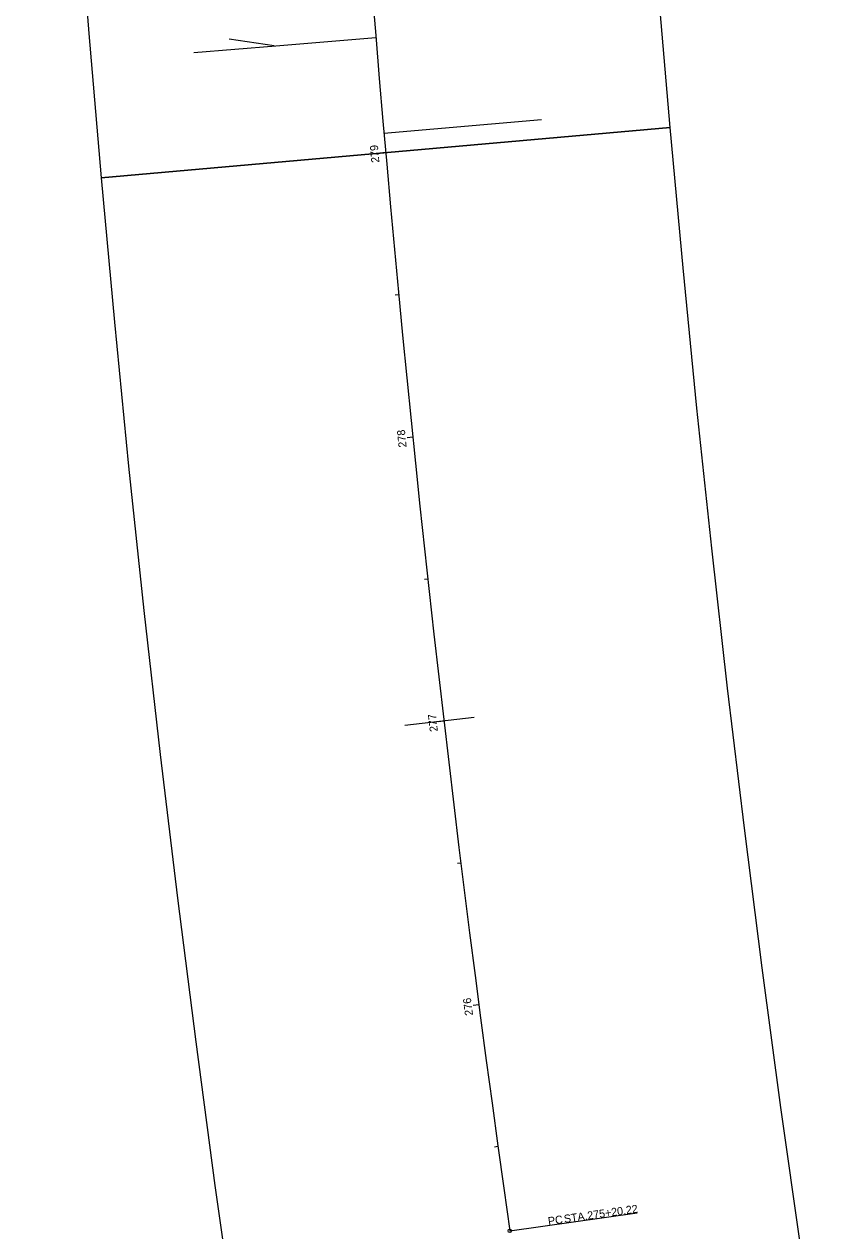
# Model space of a CAD drawing. Extents: x 1722814 to 1723176, y 329127 to 332105.
# Drawn here: x 1722817.9 to 1723103.9, y 330450.2 to 330872.4 of the extents above; entities that cross this region are included whole.
import ezdxf

# ---------------------------------------------------------------- set-up
doc = ezdxf.new("R2010")
doc.units = 0
for name, color, linetype in [('DR_P_Cells', 7, 'Continuous'), ('DR_P_Storm_Sewer', 7, 'Continuous'), ('DR_X_Cells', 7, 'Continuous'), ('DT_X_Triangles', 7, 'Continuous'), ('GE_P_Alignment', 7, 'Continuous'), ('HY_X_Wetland_Cells', 7, 'Continuous'), ('Wetland', 7, 'Continuous')]:
    doc.layers.add(name, color=color, linetype=linetype)

msp = doc.modelspace()

# ---------------------------------------------------------------- linework, layer by layer
at = {"layer": 'DR_P_Cells'}
for p, q in [((1722944.5, 330827.47), (1722942.51, 330827.29)), ((1722949.08, 330777.68), (1722947.88, 330777.57)), ((1722954, 330727.92), (1722952.01, 330727.72)), ((1722959.27, 330678.2), (1722958.07, 330678.07)), ((1722964.88, 330628.52), (1722962.9, 330628.29)), ((1722970.85, 330578.88), (1722969.66, 330578.73)), ((1722977.16, 330529.27), (1722975.17, 330529.02)), ((1722983.81, 330479.72), (1722982.62, 330479.56))]:
    msp.add_line(p, q, dxfattribs=at)
at = {"layer": 'DR_P_Storm_Sewer'}
msp.add_line((1722975.5, 330629.83), (1722951.16, 330626.99), dxfattribs=at)
at = {"layer": 'DR_X_Cells'}
for points in [[(1722844.89, 330818.67), (1723044.12, 330836.27), (1723039.95, 330885.4), (1723036.12, 330934.55), (1723032.64, 330983.73), (1723029.5, 331032.93), (1723026.71, 331082.15), (1723024.26, 331131.39), (1723022.15, 331180.65), (1723020.39, 331229.92), (1723018.97, 331279.2), (1723017.9, 331328.49), (1722817.93, 331324.83), (1722819.04, 331274.14), (1722820.49, 331223.47), (1722822.31, 331172.8), (1722824.47, 331122.15), (1722826.99, 331071.52), (1722829.87, 331020.9), (1722833.09, 330970.3), (1722836.67, 330919.73), (1722840.61, 330869.19)], [(1722905.85, 330317.14), (1723103.86, 330345.27), (1723096.82, 330394.77), (1723089.79, 330444.28), (1723082.87, 330493.38), (1723076.31, 330542.24), (1723070.09, 330591.15), (1723064.21, 330640.1), (1723058.67, 330689.09), (1723053.48, 330738.11), (1723048.63, 330787.18), (1723044.12, 330836.27), (1722844.89, 330818.67), (1722849.53, 330768.18), (1722854.52, 330717.73), (1722859.86, 330667.32), (1722865.56, 330616.94), (1722871.6, 330566.6), (1722878, 330516.31), (1722884.75, 330466.06), (1722891.78, 330416.14), (1722898.81, 330366.64)]]:
    msp.add_lwpolyline(points, close=True, dxfattribs=at)
at = {"layer": 'DT_X_Triangles'}
msp.add_line((1722905.43, 330864.84), (1722889.74, 330867.17), dxfattribs=at)
at = {"layer": 'GE_P_Alignment'}
for p, q in [((1722906.07, 330864.75), (1722877.37, 330862.38)), ((1722941.07, 330867.64), (1722906.07, 330864.75)), ((1722941.07, 330867.64), (1722906.07, 330864.75)), ((1722943.91, 330834.26), (1722999.05, 330839.08))]:
    msp.add_line(p, q, dxfattribs=at)
at = {"layer": 'HY_X_Wetland_Cells'}
msp.add_line((1722987.94, 330450.23), (1723032.49, 330456.56), dxfattribs=at)
msp.add_circle((1722987.94, 330450.23), 0.6, dxfattribs=at)
at = {"layer": 'Wetland'}
msp.add_arc((1730078.68, 331457.77), 7161.97, 180.391728, 188.087121, dxfattribs=at)
msp.add_arc((1730078.68, 331457.77), 7161.97, 180.391728, 188.087121, dxfattribs=at)

# ---------------------------------------------------------------- texts
at = {"layer": 'DR_P_Cells'}
for s, rotation, p in [('279', 95.0489, (1722942.3, 330824.04)), ('278', 95.8489, (1722951.84, 330724.44)), ('277', 96.6489, (1722962.78, 330625.01)), ('276', 97.4489, (1722975.1, 330525.72))]:
    msp.add_text(s, height=2.8, rotation=rotation, dxfattribs=at).set_placement(p)
at = {"layer": 'HY_X_Wetland_Cells'}
for s, p in [('275+20.22', (1723015.3, 330454.16)), ('PC', (1723001.52, 330452.2)), (' STA. ', (1723006.07, 330452.84))]:
    msp.add_text(s, height=2.8, rotation=8.0871, dxfattribs=at).set_placement(p)

doc.saveas('drawing.dxf')
